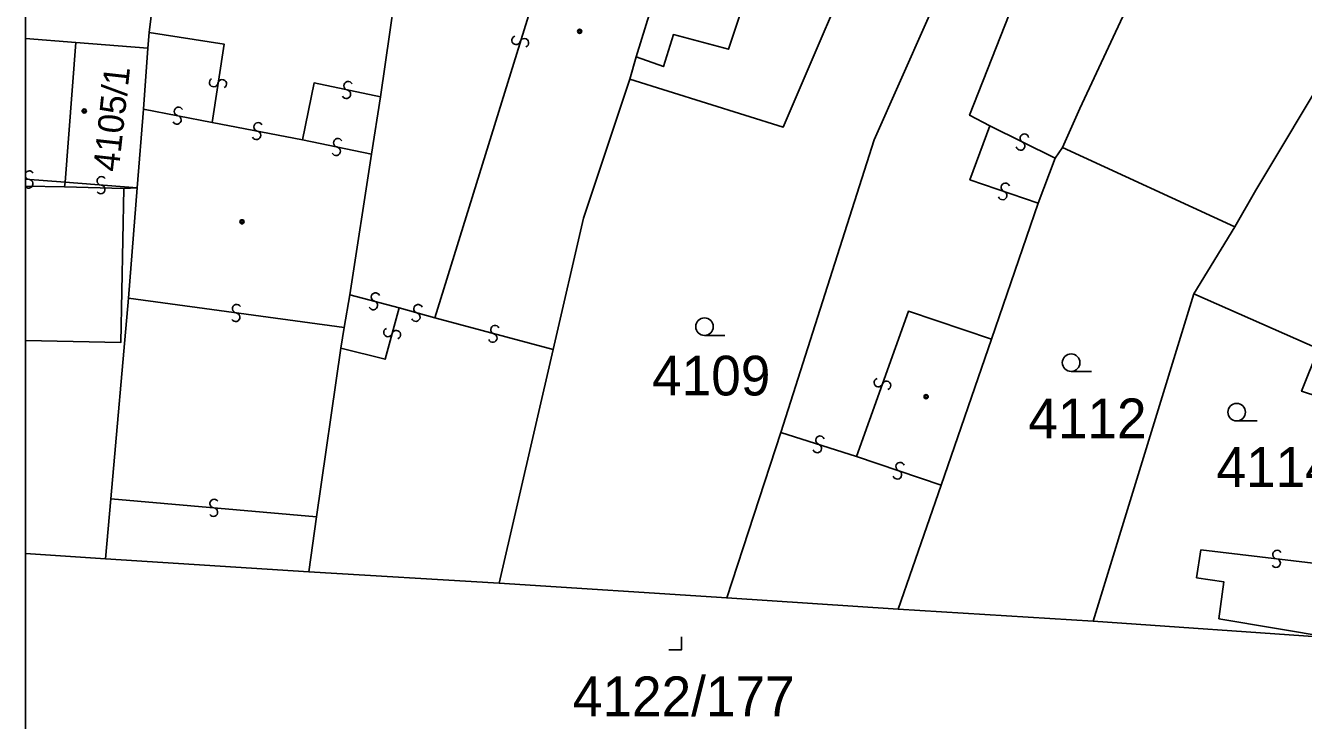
# Model space of a CAD drawing. Extents: x -598233 to -596890, y -1157848 to -1156431.
# Drawn here: x -598232.9 to -598178.2, y -1157451 to -1157421.3 of the extents above; entities that cross this region are included whole.
import ezdxf

# ---------------------------------------------------------------- set-up
doc = ezdxf.new("R2010")
doc.units = 0
for name, color, linetype in [('Level 1', 7, 'Continuous'), ('Level 13', 7, 'Continuous'), ('Level 3', 7, 'Continuous'), ('Level 4', 7, 'Continuous'), ('Level 5', 7, 'Continuous'), ('Level 60', 7, 'Continuous'), ('Vrstva 60', 7, 'Continuous'), ('zajmove_uzemi', 7, 'Continuous')]:
    doc.layers.add(name, color=color, linetype=linetype)

msp = doc.modelspace()

# ---------------------------------------------------------------- linework, layer by layer
at = {"layer": 'Level 1'}
for p, q in [((-598232.89, -1157421.835), (-598230.74, -1157422.01)), ((-598232.89, -1157428.153), (-598231.22, -1157428.18)), ((-598232.89, -1157443.864), (-598229.47, -1157444.1))]:
    msp.add_line(p, q, dxfattribs=at)
for points in [[(-598180.96, -1157410.17), (-598187.8, -1157424.83), (-598188.54, -1157426.5)], [(-598170.48, -1157409.91), (-598172.54, -1157413.94), (-598176.02, -1157420.94), (-598177.05, -1157422.95), (-598180.27, -1157428.33), (-598181.17, -1157429.9)], [(-598203.21, -1157411.09), (-598206.78, -1157422.62)], [(-598193.22, -1157418.55), (-598196.79, -1157417.01), (-598200.48, -1157425.63), (-598207.05, -1157423.58)], [(-598216.73, -1157417.5), (-598217.71, -1157424.34)], [(-598193.22, -1157418.55), (-598196.59, -1157426.18), (-598200.59, -1157438.69)], [(-598227.33, -1157419.35), (-598227.61, -1157421.58)], [(-598227.61, -1157421.58), (-598227.66, -1157422.25)], [(-598230.74, -1157422.01), (-598231.2, -1157427.99)], [(-598227.66, -1157422.25), (-598230.74, -1157422.01)], [(-598227.85, -1157424.86), (-598227.66, -1157422.25)], [(-598206.78, -1157422.62), (-598207.05, -1157423.58)], [(-598207.05, -1157423.58), (-598209.02, -1157429.53), (-598210.32, -1157435.15)], [(-598217.71, -1157424.34), (-598218.1, -1157426.78)], [(-598227.85, -1157424.86), (-598228.12, -1157428.23)], [(-598188.54, -1157426.5), (-598188.85, -1157426.96)], [(-598181.17, -1157429.9), (-598188.54, -1157426.5)], [(-598218.1, -1157426.78), (-598219.02, -1157432.8)], [(-598188.85, -1157426.96), (-598189.58, -1157428.88)], [(-598228.69, -1157428.25), (-598228.81, -1157434.84), (-598232.89, -1157434.763)], [(-598231.2, -1157427.99), (-598231.22, -1157428.18)], [(-598231.22, -1157428.18), (-598228.69, -1157428.25)], [(-598228.12, -1157428.23), (-598228.69, -1157428.25)], [(-598228.49, -1157432.95), (-598228.12, -1157428.23)], [(-598189.58, -1157428.88), (-598191.58, -1157434.7)], [(-598181.17, -1157429.9), (-598182.92, -1157432.76)], [(-598229.24, -1157441.53), (-598228.49, -1157432.95)], [(-598219.02, -1157432.8), (-598219.26, -1157434.2)], [(-598182.92, -1157432.76), (-598187.22, -1157446.77)], [(-598174.44, -1157438.19), (-598178.31, -1157436.93), (-598177.59, -1157435.11), (-598182.92, -1157432.76)], [(-598219.26, -1157434.2), (-598219.41, -1157435.09)], [(-598191.58, -1157434.7), (-598193.73, -1157440.94)], [(-598219.41, -1157435.09), (-598220.45, -1157442.3)], [(-598210.32, -1157435.15), (-598212.63, -1157445.14)], [(-598200.59, -1157438.69), (-598202.9, -1157445.77)], [(-598193.73, -1157440.94), (-598195.56, -1157446.25)], [(-598229.47, -1157444.1), (-598229.24, -1157441.53)], [(-598220.45, -1157442.3), (-598220.77, -1157444.65)], [(-598229.47, -1157444.1), (-598220.77, -1157444.65)], [(-598220.77, -1157444.65), (-598212.63, -1157445.14)], [(-598212.63, -1157445.14), (-598202.9, -1157445.77)], [(-598202.9, -1157445.77), (-598195.56, -1157446.25)], [(-598195.56, -1157446.25), (-598187.22, -1157446.77)], [(-598187.22, -1157446.77), (-598177, -1157447.48)]]:
    msp.add_lwpolyline(points, dxfattribs=at)
at = {"layer": 'Level 13'}
for centre, start, end in [((-598211.906, -1157421.914), 110.1458, 342.2438), ((-598211.554, -1157422.025), 289.9313, 162.5213), ((-598224.842, -1157423.721), 118.7166, 350.8146), ((-598224.478, -1157423.779), 298.5021, 171.0921), ((-598219.091, -1157423.86), 25.229, 257.819), ((-598219.17, -1157424.22), 205.4434, 77.5414), ((-598226.343, -1157424.959), 26.4005, 258.4985), ((-598226.416, -1157425.321), 206.186, 78.776), ((-598222.943, -1157425.619), 26.4049, 258.5029), ((-598223.016, -1157425.981), 206.1904, 78.7804), ((-598219.531, -1157426.3), 25.8381, 257.9361), ((-598190.167, -1157426.106), 10.7572, 243.3472), ((-598219.608, -1157426.66), 205.6237, 78.2137), ((-598190.334, -1157426.434), 190.9716, 63.0696), ((-598232.725, -1157427.687), 32.7027, 153.8106), ((-598232.725, -1157427.687), 206.1894, 265.2927), ((-598229.645, -1157427.927), 32.7027, 265.2927), ((-598232.756, -1157428.054), 223.392, 85.0151), ((-598229.676, -1157428.294), 212.9171, 85.0151), ((-598191.101, -1157428.554), 198.4682, 70.5662), ((-598190.98, -1157428.206), 18.2537, 250.8437), ((-598217.922, -1157432.902), 22.2945, 254.8845), ((-598223.854, -1157433.398), 29.4458, 262.0358), ((-598218.019, -1157433.258), 202.5089, 74.6069), ((-598216.099, -1157433.403), 21.3624, 253.9524), ((-598223.906, -1157433.763), 209.6602, 81.7582), ((-598216.202, -1157433.757), 201.5768, 73.6748), ((-598217.387, -1157434.411), 111.9032, 344.4932), ((-598217.033, -1157434.51), 292.1176, 164.2156), ((-598212.812, -1157434.292), 22.1425, 254.7325), ((-598212.909, -1157434.648), 202.3569, 74.4549), ((-598196.413, -1157436.556), 107.7014, 339.7994), ((-598196.067, -1157436.683), 287.4869, 160.0769), ((-598199.027, -1157439.375), 199.5228, 72.1128), ((-598198.912, -1157439.025), 19.7372, 251.8352), ((-598195.601, -1157440.504), 198.7481, 70.8461), ((-598195.48, -1157440.156), 18.5336, 251.1236), ((-598224.857, -1157442.103), 212.152, 84.742), ((-598224.822, -1157441.736), 32.3664, 264.4644), ((-598179.403, -1157444.283), 210.3818, 82.9718), ((-598179.357, -1157443.917), 30.5962, 262.6942)]:
    msp.add_arc(centre, 0.184, start, end, dxfattribs=at)
at = {"layer": 'Level 3'}
msp.add_line((-598231.2, -1157427.99), (-598232.89, -1157427.858), dxfattribs=at)
for points in [[(-598215.39, -1157433.79), (-598208.06, -1157410.15)], [(-598191.65, -1157425.57), (-598192.51, -1157425.12), (-598187.58, -1157412.59), (-598190.12, -1157411.46)], [(-598199.79, -1157416.03), (-598200.61, -1157415.66), (-598202.83, -1157422.3), (-598205.18, -1157421.67), (-598205.61, -1157423.04), (-598206.78, -1157422.62)], [(-598224.91, -1157425.43), (-598224.4, -1157422.08), (-598227.61, -1157421.58)], [(-598217.71, -1157424.34), (-598220.55, -1157423.74), (-598221.04, -1157426.18)], [(-598227.85, -1157424.86), (-598224.91, -1157425.43)], [(-598224.91, -1157425.43), (-598221.04, -1157426.18)], [(-598189.58, -1157428.88), (-598192.5, -1157427.88), (-598191.65, -1157425.57)], [(-598188.85, -1157426.96), (-598191.65, -1157425.57)], [(-598221.04, -1157426.18), (-598218.1, -1157426.78)], [(-598228.12, -1157428.23), (-598231.2, -1157427.99)], [(-598219.26, -1157434.2), (-598228.49, -1157432.95)], [(-598216.91, -1157433.36), (-598219.02, -1157432.8)], [(-598216.91, -1157433.36), (-598217.51, -1157435.56), (-598219.41, -1157435.09)], [(-598215.39, -1157433.79), (-598216.91, -1157433.36)], [(-598210.32, -1157435.15), (-598215.39, -1157433.79)], [(-598197.35, -1157439.72), (-598195.13, -1157433.51), (-598191.58, -1157434.7)], [(-598200.59, -1157438.69), (-598197.35, -1157439.72)], [(-598193.73, -1157440.94), (-598197.35, -1157439.72)], [(-598229.24, -1157441.53), (-598220.45, -1157442.3)], [(-598177, -1157447.48), (-598181.85, -1157446.66), (-598181.64, -1157445.08), (-598182.8, -1157444.91), (-598182.62, -1157443.72), (-598176.14, -1157444.49)]]:
    msp.add_lwpolyline(points, dxfattribs=at)
at = {"layer": 'Level 5'}
for p, q in [((-598203.85, -1157434.54), (-598202.975, -1157434.54)), ((-598188.17, -1157436.08), (-598187.295, -1157436.08)), ((-598181.09, -1157438.2), (-598180.215, -1157438.2))]:
    msp.add_line(p, q, dxfattribs=at)
msp.add_lwpolyline([(-598205.38, -1157447.99), (-598204.83, -1157447.99), (-598204.83, -1157447.44)], dxfattribs=at)
for centre, radius in [((-598209.19, -1157421.53), 0.09), ((-598209.19, -1157421.53), 0.0521), ((-598230.38, -1157424.94), 0.09), ((-598230.38, -1157424.94), 0.0521), ((-598223.63, -1157429.68), 0.09), ((-598223.63, -1157429.68), 0.0521), ((-598203.85, -1157434.165), 0.375), ((-598188.17, -1157435.705), 0.375), ((-598194.37, -1157437.16), 0.09), ((-598194.37, -1157437.16), 0.0521), ((-598181.09, -1157437.825), 0.375)]:
    msp.add_circle(centre, radius, dxfattribs=at)
at = {"layer": 'Level 60'}
for points in [[(-598213, -1157406.69), (-598209.77, -1157396.86), (-598199.57, -1157401.58), (-598203.21, -1157411.09), (-598206.78, -1157422.62), (-598207.05, -1157423.58), (-598209.02, -1157429.53), (-598210.32, -1157435.15), (-598212.63, -1157445.14), (-598220.77, -1157444.65), (-598220.45, -1157442.3), (-598219.41, -1157435.09), (-598219.26, -1157434.2), (-598219.02, -1157432.8), (-598218.1, -1157426.78), (-598217.71, -1157424.34), (-598216.73, -1157417.5), (-598213.45, -1157407.72)], [(-598203.21, -1157411.09), (-598199.57, -1157401.58), (-598195.21, -1157403.58), (-598188.1, -1157406.86), (-598190.12, -1157411.46), (-598192.12, -1157416.08), (-598193.22, -1157418.55), (-598196.79, -1157417.01), (-598200.48, -1157425.63), (-598207.05, -1157423.58), (-598206.78, -1157422.62)], [(-598190.12, -1157411.46), (-598188.1, -1157406.86), (-598186.38, -1157402.97), (-598185, -1157403.54), (-598179.09, -1157406.13), (-598180.96, -1157410.17), (-598187.8, -1157424.83), (-598188.54, -1157426.5), (-598188.85, -1157426.96), (-598189.58, -1157428.88), (-598191.58, -1157434.7), (-598193.73, -1157440.94), (-598195.56, -1157446.25), (-598202.9, -1157445.77), (-598200.59, -1157438.69), (-598196.59, -1157426.18), (-598193.22, -1157418.55), (-598192.12, -1157416.08)], [(-598180.96, -1157410.17), (-598179.09, -1157406.13), (-598176.37, -1157407.32), (-598174.79, -1157407.97), (-598170.48, -1157409.91), (-598172.54, -1157413.94), (-598176.02, -1157420.94), (-598177.05, -1157422.95), (-598180.27, -1157428.33), (-598181.17, -1157429.9), (-598188.54, -1157426.5), (-598187.8, -1157424.83)], [(-598172.54, -1157413.94), (-598170.48, -1157409.91), (-598167.1, -1157410.4), (-598169.96, -1157417.61), (-598171.54, -1157420.97), (-598172.79, -1157423.51), (-598169.58, -1157425.35), (-598173.19, -1157433.95), (-598174.44, -1157438.19), (-598178.31, -1157436.93), (-598177.59, -1157435.11), (-598182.92, -1157432.76), (-598181.17, -1157429.9), (-598180.27, -1157428.33), (-598177.05, -1157422.95), (-598176.02, -1157420.94)], [(-598209.02, -1157429.53), (-598207.05, -1157423.58), (-598200.48, -1157425.63), (-598196.79, -1157417.01), (-598193.22, -1157418.55), (-598196.59, -1157426.18), (-598200.59, -1157438.69), (-598202.9, -1157445.77), (-598212.63, -1157445.14), (-598210.32, -1157435.15)], [(-598227.85, -1157424.86), (-598228.12, -1157428.23), (-598228.69, -1157428.25), (-598231.22, -1157428.18), (-598231.2, -1157427.99), (-598230.74, -1157422.01), (-598227.66, -1157422.25)], [(-598188.85, -1157426.96), (-598188.54, -1157426.5), (-598181.17, -1157429.9), (-598182.92, -1157432.76), (-598187.22, -1157446.77), (-598195.56, -1157446.25), (-598193.73, -1157440.94), (-598191.58, -1157434.7), (-598189.58, -1157428.88)], [(-598187.22, -1157446.77), (-598182.92, -1157432.76), (-598177.59, -1157435.11), (-598178.31, -1157436.93), (-598174.44, -1157438.19), (-598176.14, -1157444.49), (-598176.43, -1157445.58), (-598177, -1157447.48)]]:
    msp.add_lwpolyline(points, close=True, dxfattribs=at)
msp.add_lwpolyline([(-598216.73, -1157417.5), (-598217.71, -1157424.34), (-598218.1, -1157426.78), (-598219.02, -1157432.8), (-598219.26, -1157434.2), (-598219.41, -1157435.09), (-598220.45, -1157442.3), (-598220.77, -1157444.65), (-598229.47, -1157444.1), (-598229.24, -1157441.53), (-598228.49, -1157432.95), (-598228.12, -1157428.23), (-598227.85, -1157424.86), (-598227.66, -1157422.25), (-598227.61, -1157421.58), (-598227.33, -1157419.35)], dxfattribs=at)
at = {"layer": 'Vrstva 60'}
for points in [[(-598232.89, -1156430.856), (-598232.89, -1157835.582), (-598232.81, -1157835.6), (-598231.24, -1157835.95), (-598223.73, -1157837.73), (-598218.75, -1157838.85), (-598190.54, -1157845.18), (-598175.89, -1157848.461), (-598170.508, -1157848.461), (-598170.38, -1157848.22), (-598166.89, -1157841.65), (-598165.3, -1157838.66), (-598164.37, -1157836.9), (-598161.86, -1157832.18), (-598161.19, -1157830.95), (-598160.05, -1157828.86), (-598157.63, -1157824.55), (-598144.71, -1157839.14), (-598136.407, -1157848.461), (-597003.664, -1157848.461)], [(-598170.43, -1157455.49), (-598169.88, -1157447.85), (-598171.71, -1157447.77), (-598177, -1157447.48), (-598187.22, -1157446.77), (-598195.56, -1157446.25), (-598202.9, -1157445.77), (-598212.63, -1157445.14), (-598220.77, -1157444.65), (-598229.47, -1157444.1), (-598232.89, -1157443.864), (-598232.89, -1157451.105)]]:
    msp.add_lwpolyline(points, dxfattribs=at)
for points in [[(-598232.89, -1157409.602), (-598232.89, -1157421.835), (-598230.74, -1157422.01), (-598227.66, -1157422.25), (-598227.61, -1157421.58), (-598227.33, -1157419.35), (-598227.06, -1157414.92), (-598226.27, -1157412.82), (-598228.7, -1157412.04), (-598228.26, -1157410.82)], [(-598232.89, -1157421.835), (-598232.89, -1157428.153), (-598231.22, -1157428.18), (-598231.2, -1157427.99), (-598230.74, -1157422.01)], [(-598232.89, -1157428.153), (-598232.89, -1157434.763), (-598228.81, -1157434.84), (-598228.69, -1157428.25), (-598231.22, -1157428.18)], [(-598232.89, -1157434.763), (-598232.89, -1157443.864), (-598229.47, -1157444.1), (-598229.24, -1157441.53), (-598228.49, -1157432.95), (-598228.12, -1157428.23), (-598228.69, -1157428.25), (-598228.81, -1157434.84)]]:
    msp.add_lwpolyline(points, close=True, dxfattribs=at)
at = {"layer": 'zajmove_uzemi'}
msp.add_lwpolyline([(-598232.89, -1156430.856), (-596890.462, -1156430.856), (-596890.462, -1157848.461), (-598232.89, -1157848.461)], close=True, dxfattribs=at)

# ---------------------------------------------------------------- texts
at = {"layer": 'Level 4'}
msp.add_text('4105/1', height=1.1, rotation=83.7, dxfattribs=at).set_placement((-598228.91, -1157427.57))
for s, p in [('4109', (-598206.09, -1157437.11)), ('4112', (-598190, -1157438.94)), ('4114', (-598181.95, -1157441.02)), ('4122/177', (-598209.479, -1157450.83))]:
    msp.add_text(s, height=1.7, dxfattribs=at).set_placement(p)

doc.saveas('drawing.dxf')
